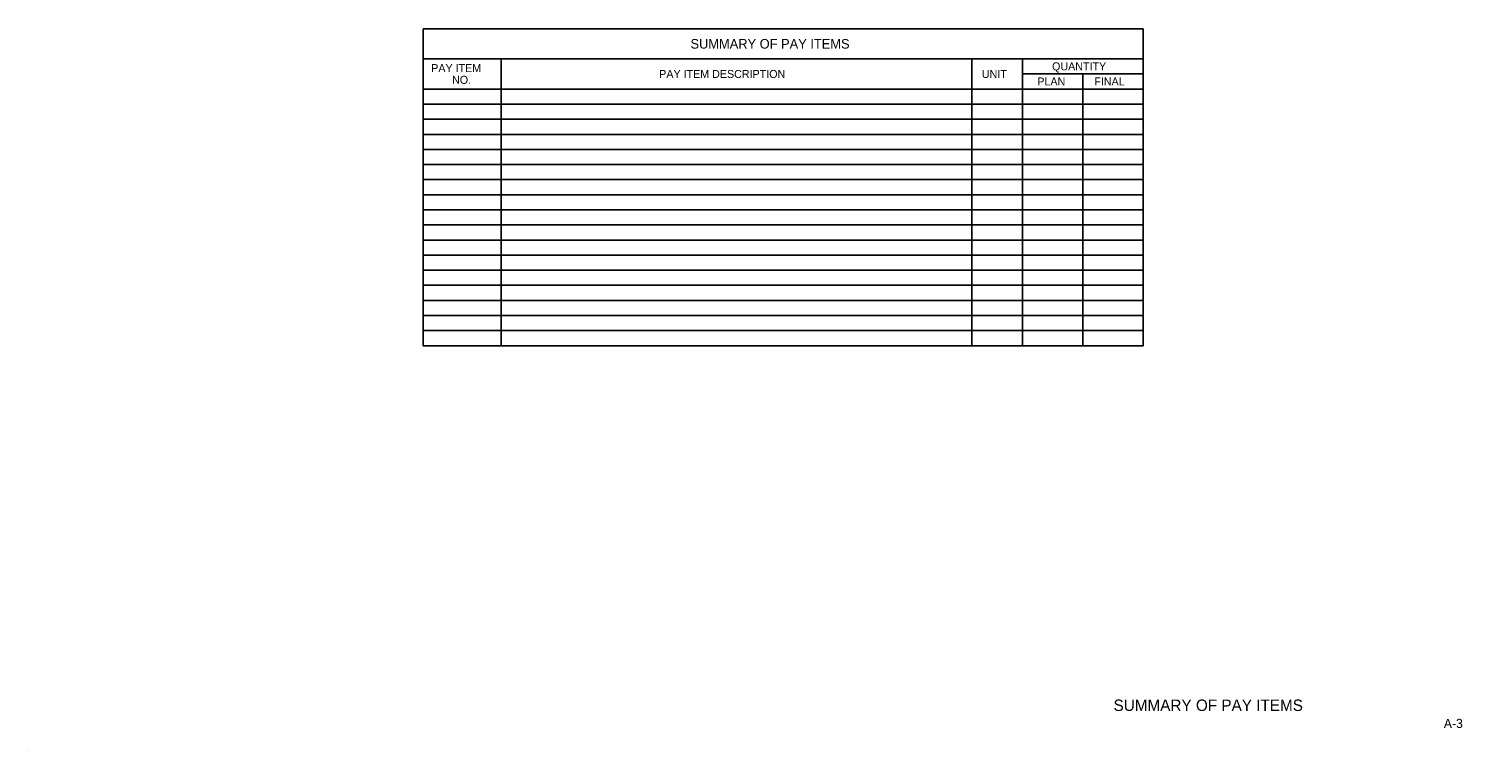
# Model space of a CAD drawing. Extents: x -830008.4 to -829992.7, y 1290284.1 to 1290292.
import ezdxf

# ---------------------------------------------------------------- set-up
doc = ezdxf.new("R2010")
doc.units = 0
for name, color, linetype in [('AdhocPoint_dp', 7, 'Continuous'), ('SumBoxBorder_dp', 7, 'Continuous'), ('SumBoxLines_dp', 7, 'Continuous'), ('SumBoxLinesMin_dp', 7, 'Continuous'), ('TextLabel', 7, 'Continuous'), ('TextMisc', 7, 'Continuous'), ('TextShtNo', 7, 'Continuous')]:
    doc.layers.add(name, color=color, linetype=linetype)

msp = doc.modelspace()

# ---------------------------------------------------------------- linework, layer by layer
at = {"layer": 'AdhocPoint_dp'}
msp.add_line((-830008.374, 1290284.078), (-830008.374, 1290284.078), dxfattribs=at)
at = {"layer": 'SumBoxBorder_dp'}
for p, q in [((-830004.062, 1290291.977), (-829996.187, 1290291.977)), ((-830004.062, 1290291.977), (-830004.062, 1290288.512)), ((-829996.187, 1290291.977), (-829996.187, 1290288.512)), ((-830004.062, 1290288.512), (-829996.187, 1290288.512))]:
    msp.add_line(p, q, dxfattribs=at)
at = {"layer": 'SumBoxLines_dp'}
for p, q in [((-830004.062, 1290291.647), (-829996.187, 1290291.647)), ((-830003.207, 1290291.647), (-830003.207, 1290288.512)), ((-830003.207, 1290291.647), (-830003.207, 1290288.512)), ((-829998.062, 1290291.647), (-829998.062, 1290288.512)), ((-829998.062, 1290291.647), (-829998.062, 1290288.512)), ((-829997.507, 1290291.647), (-829997.507, 1290288.512)), ((-829997.507, 1290291.647), (-829997.507, 1290288.512)), ((-829997.507, 1290291.482), (-829996.187, 1290291.482)), ((-829997.507, 1290291.482), (-829996.187, 1290291.482)), ((-829996.847, 1290291.482), (-829996.847, 1290288.512)), ((-829996.847, 1290291.482), (-829996.847, 1290288.512)), ((-830004.062, 1290291.317), (-829996.187, 1290291.317)), ((-830004.062, 1290291.317), (-829996.187, 1290291.317))]:
    msp.add_line(p, q, dxfattribs=at)
at = {"layer": 'SumBoxLinesMin_dp'}
for p, q in [((-830004.062, 1290291.152), (-829996.187, 1290291.152)), ((-830004.062, 1290291.152), (-829996.187, 1290291.152)), ((-830004.062, 1290290.987), (-829996.187, 1290290.987)), ((-830004.062, 1290290.987), (-829996.187, 1290290.987)), ((-830004.062, 1290290.822), (-829996.187, 1290290.822)), ((-830004.062, 1290290.822), (-829996.187, 1290290.822)), ((-830004.062, 1290290.657), (-829996.187, 1290290.657)), ((-830004.062, 1290290.657), (-829996.187, 1290290.657)), ((-830004.062, 1290290.492), (-829996.187, 1290290.492)), ((-830004.062, 1290290.492), (-829996.187, 1290290.492)), ((-830004.062, 1290290.327), (-829996.187, 1290290.327)), ((-830004.062, 1290290.327), (-829996.187, 1290290.327)), ((-830004.062, 1290290.162), (-829996.187, 1290290.162)), ((-830004.062, 1290290.162), (-829996.187, 1290290.162)), ((-830004.062, 1290289.997), (-829996.187, 1290289.997)), ((-830004.062, 1290289.997), (-829996.187, 1290289.997)), ((-830004.062, 1290289.832), (-829996.187, 1290289.832)), ((-830004.062, 1290289.832), (-829996.187, 1290289.832)), ((-830004.062, 1290289.667), (-829996.187, 1290289.667)), ((-830004.062, 1290289.667), (-829996.187, 1290289.667)), ((-830004.062, 1290289.502), (-829996.187, 1290289.502)), ((-830004.062, 1290289.502), (-829996.187, 1290289.502)), ((-830004.062, 1290289.337), (-829996.187, 1290289.337)), ((-830004.062, 1290289.337), (-829996.187, 1290289.337)), ((-830004.062, 1290289.172), (-829996.187, 1290289.172)), ((-830004.062, 1290289.172), (-829996.187, 1290289.172)), ((-830004.062, 1290289.007), (-829996.187, 1290289.007)), ((-830004.062, 1290289.007), (-829996.187, 1290289.007)), ((-830004.062, 1290288.842), (-829996.187, 1290288.842)), ((-830004.062, 1290288.842), (-829996.187, 1290288.842)), ((-830004.062, 1290288.677), (-829996.187, 1290288.677)), ((-830004.062, 1290288.677), (-829996.187, 1290288.677))]:
    msp.add_line(p, q, dxfattribs=at)

# ---------------------------------------------------------------- texts
at = {"layer": 'TextLabel'}
for s, height, p in [('SUMMARY OF PAY ITEMS', 0.105, (-830001.137, 1290291.759)), ('PAY ITEM', 0.0875, (-830003.972, 1290291.502)), ('PAY ITEM DESCRIPTION', 0.0875, (-830001.479, 1290291.438)), ('UNIT', 0.0875, (-829997.951, 1290291.438)), ('QUANTITY', 0.0875, (-829997.183, 1290291.521)), ('NO.', 0.0875, (-830003.744, 1290291.374)), ('PLAN', 0.0875, (-829997.344, 1290291.356)), ('FINAL', 0.0875, (-829996.721, 1290291.356))]:
    msp.add_text(s, height=height, dxfattribs=at).set_placement(p)
at = {"layer": 'TextMisc'}
msp.add_text('     SUMMARY OF PAY ITEMS      ', height=0.125, dxfattribs=at).set_placement((-829996.743, 1290284.519))
at = {"layer": 'TextShtNo'}
msp.add_text('A-3', height=0.1, dxfattribs=at).set_placement((-829992.899, 1290284.333))

doc.saveas('drawing.dxf')
